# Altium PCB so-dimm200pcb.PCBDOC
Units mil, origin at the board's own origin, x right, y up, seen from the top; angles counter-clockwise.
Board outline 6000 x 4000 mil, 2 copper layers (Top Layer, Bottom Layer); 3 components, 0 nets, 611 pads, 0 vias.
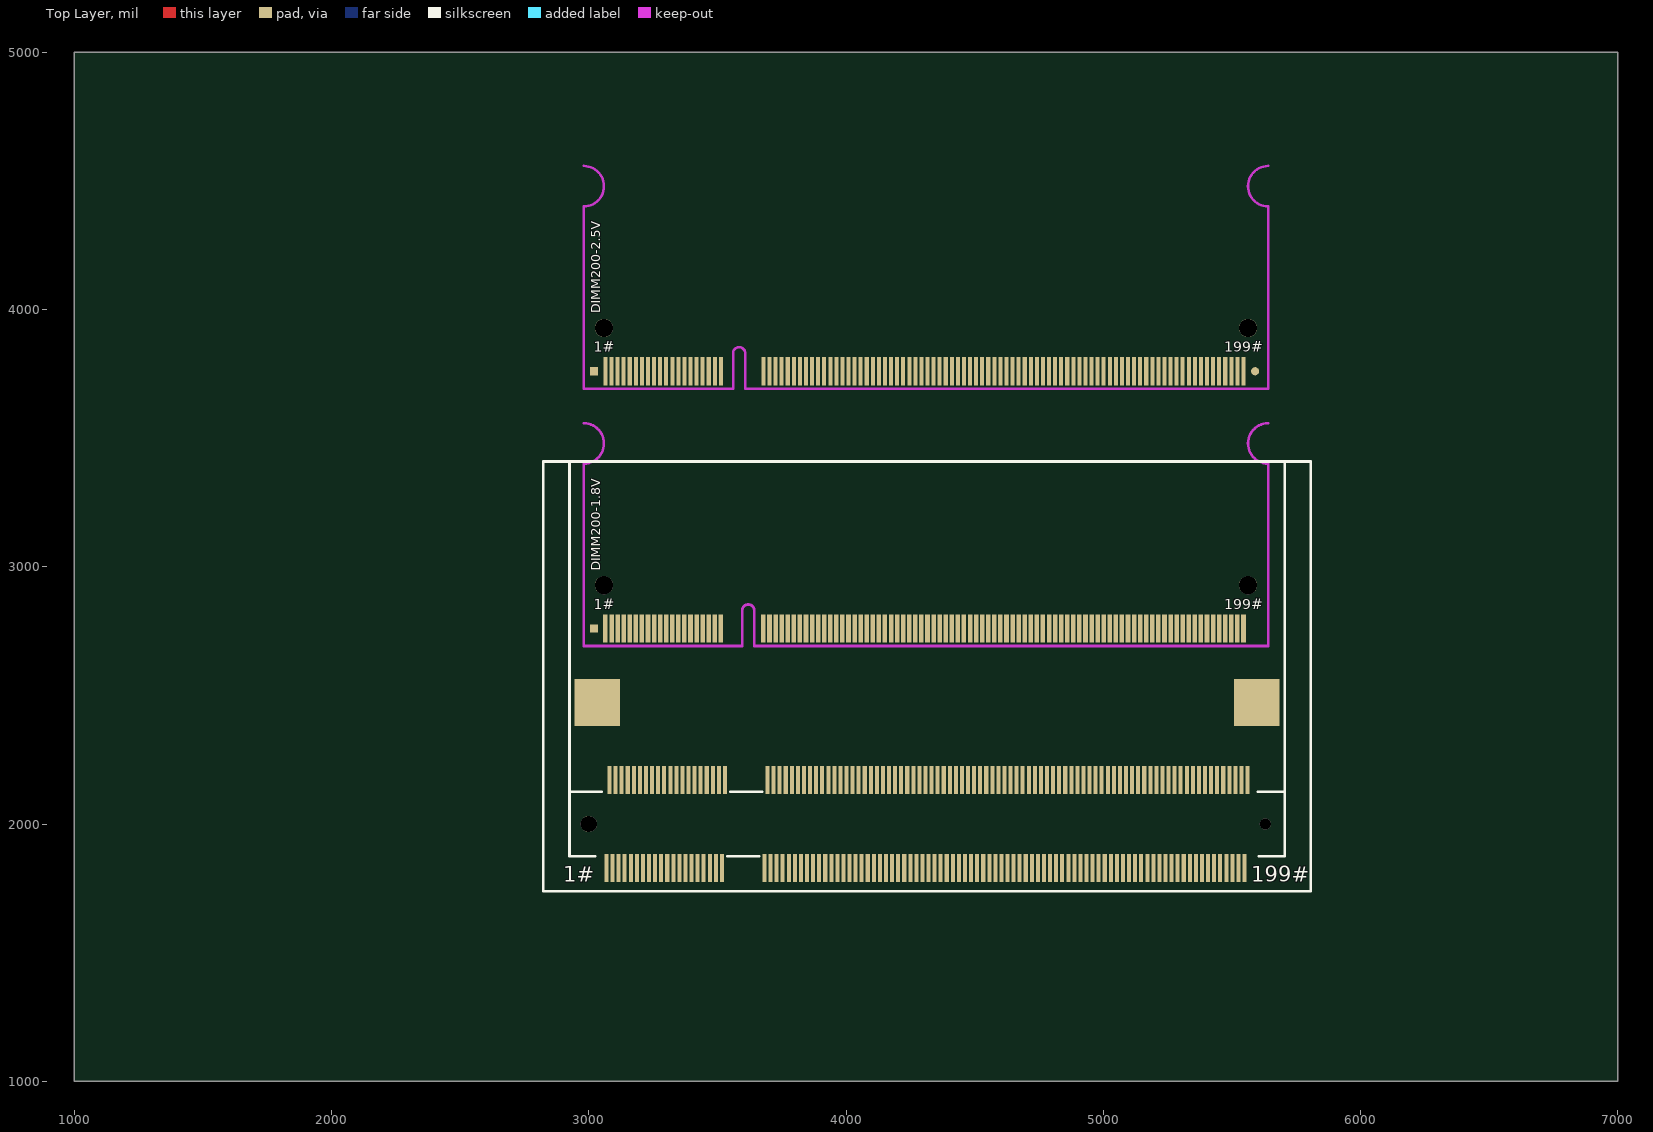
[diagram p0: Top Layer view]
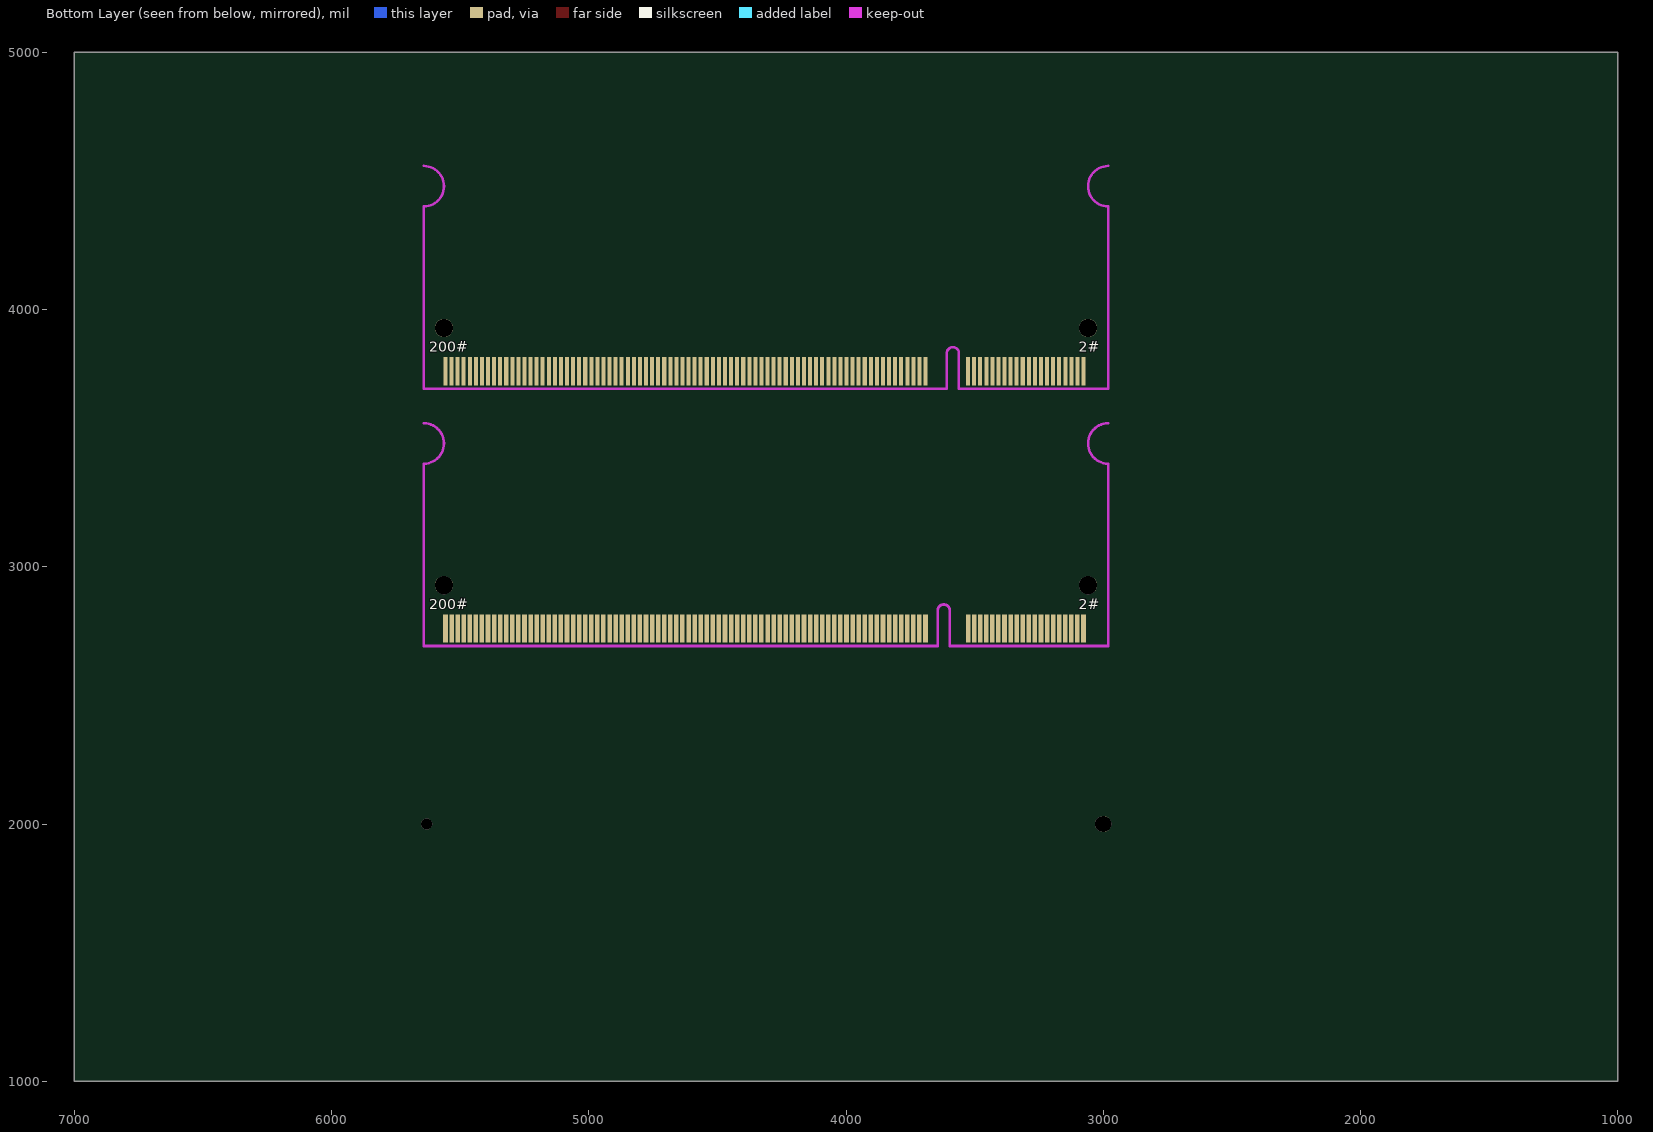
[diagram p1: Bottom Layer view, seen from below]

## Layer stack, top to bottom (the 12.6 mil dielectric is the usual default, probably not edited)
Top Layer: signal copper 1.4
Dielectric: dielectric 12.6, FR-4, Dk 4.8
Bottom Layer: signal copper 1.4

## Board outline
1000,1000 7000,1000 7000,5000 1000,5000

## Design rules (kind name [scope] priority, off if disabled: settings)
Clearance [All] p1: gap=10
ComponentClearance [All] p1: gap=10 collisioncheckmode=0
PolygonConnect [All] p1: connectstyle=Relief reliefconductorwidth=10 reliefentries=4 polygonreliefangle="90 Angle"
RoutingLayers [All] p1: top layer=Horizontal bottom layer=Vertical
RoutingVias [All] p1: holewidth=28 width=50 viastyle="Through Hole" minholewidth=28 minwidth=50 maxholewidth=28 maxwidth=50
SolderMaskExpansion [All] p1: expansion=4
TestPointUsage [All] p1: valid=0 allowmultiple=FALSE
Testpoint [All] p1: side=15 testpointundercomponent=TRUE minsize=40 maxsize=100 preferedsize=60 minholesize=0 maxholesize=40 preferedholesize=32 testpointgrid=1 style=1023 order=1234567890
Width [All] p1: maxlimit=10 minlimit=10 preferedwidth=10
16 further rules are at their usual default settings.

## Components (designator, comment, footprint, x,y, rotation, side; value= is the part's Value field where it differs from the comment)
? "Comment" "SO-DIMM200V25 " 3620,3760 r0 top
? "Comment" SO-DIMM200 3620,2760 r0 top
? "Comment" so-dimm200x 3000,2000 r0 top

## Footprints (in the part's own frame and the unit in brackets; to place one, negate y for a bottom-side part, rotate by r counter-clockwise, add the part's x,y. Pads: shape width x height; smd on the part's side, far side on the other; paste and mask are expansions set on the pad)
SO-DIMM200 [mm]
  round 1.8 hole 1.8: 0(-14.25,4.273) 0(49.35,4.273)
  rect 0.45x2.8 smd: A1(-14.1,0) A2(-13.5,0) A3(-12.9,0) A4(-12.3,0) A5(-11.7,0) A6(-11.1,0) A7(-10.5,0) A8(-9.9,0) A9(-9.3,0) A10(-8.7,0) A11(-8.1,0) A12(-7.5,0) A13(-6.9,0) A14(-6.3,0) A15(-5.7,0) A16(-5.1,0) A17(-4.5,0) A18(-3.9,0) A19(-3.3,0) A20(-2.7,0) A21(1.5,0) A22(2.1,0) A23(2.7,0) A24(3.3,0) A25(3.9,0) A26(4.5,0) A27(5.1,0) A28(5.7,0) A29(6.3,0) A30(6.9,0) A31(7.5,0) A32(8.1,0) A33(8.7,0) A34(9.3,0) A35(9.9,0) A36(10.5,0) A37(11.1,0) A38(11.7,0) A39(12.3,0) A40(12.9,0) A41(13.5,0) A42(14.1,0) A43(14.7,0) A44(15.3,0) A45(15.9,0) A46(16.5,0) A47(17.1,0) A48(17.7,0) A49(18.3,0) A50(18.9,0) A51(19.5,0) A52(20.1,0) A53(20.7,0) A54(21.3,0) A55(21.9,0) A56(22.5,0) A57(23.1,0) A58(23.7,0) A59(24.3,0) A60(24.9,0) A61(25.5,0) A62(26.1,0) A63(26.7,0) A64(27.3,0) A65(27.9,0) A66(28.5,0) A67(29.1,0) A68(29.7,0) A69(30.3,0) A70(30.9,0) A71(31.5,0) A72(32.1,0) A73(32.7,0) A74(33.3,0) A75(33.9,0) A76(34.5,0) A77(35.1,0) A78(35.7,0) A79(36.3,0) A80(36.9,0) A81(37.5,0) A82(38.1,0) A83(38.7,0) A84(39.3,0) A85(39.9,0) A86(40.5,0) A87(41.1,0) A88(41.7,0) A89(42.3,0) A90(42.9,0) A91(43.5,0) A92(44.1,0) A93(44.7,0) A94(45.3,0) A95(45.9,0) A96(46.5,0) A97(47.1,0) A98(47.7,0) A99(48.3,0) A100(48.9,0)
  rect 0.45x2.8 smd far side: B1(-13.8,0) B2(-13.2,0) B3(-12.6,0) B4(-12,0) B5(-11.4,0) B6(-10.8,0) B7(-10.2,0) B8(-9.6,0) B9(-9,0) B10(-8.4,0) B11(-7.8,0) B12(-7.2,0) B13(-6.6,0) B14(-6,0) B15(-5.4,0) B16(-4.8,0) B17(-4.2,0) B18(-3.6,0) B19(-3,0) B20(-2.4,0) B21(1.8,0) B22(2.4,0) B23(3,0) B24(3.6,0) B25(4.2,0) B26(4.8,0) B27(5.4,0) B28(6,0) B29(6.6,0) B30(7.2,0) B31(7.8,0) B32(8.4,0) B33(9,0) B34(9.6,0) B35(10.2,0) B36(10.8,0) B37(11.4,0) B38(12,0) B39(12.6,0) B40(13.2,0) B41(13.8,0) B42(14.4,0) B43(15,0) B44(15.6,0) B45(16.2,0) B46(16.8,0) B47(17.4,0) B48(18,0) B49(18.6,0) B50(19.2,0) B51(19.8,0) B52(20.4,0) B53(21,0) B54(21.6,0) B55(22.2,0) B56(22.8,0) B57(23.4,0) B58(24,0) B59(24.6,0) B60(25.2,0) B61(25.8,0) B62(26.4,0) B63(27,0) B64(27.6,0) B65(28.2,0) B66(28.8,0) B67(29.4,0) B68(30,0) B69(30.6,0) B70(31.2,0) B71(31.8,0) B72(32.4,0) B73(33,0) B74(33.6,0) B75(34.2,0) B76(34.8,0) B77(35.4,0) B78(36,0) B79(36.6,0) B80(37.2,0) B81(37.8,0) B82(38.4,0) B83(39,0) B84(39.6,0) B85(40.2,0) B86(40.8,0) B87(41.4,0) B88(42,0) B89(42.6,0) B90(43.2,0) B91(43.8,0) B92(44.4,0) B93(45,0) B94(45.6,0) B95(46.2,0) B96(46.8,0) B97(47.4,0) B98(48,0) B99(48.6,0) B100(49.2,0)
  rect 0.8x0.8 smd: ""(-15.24,0)
  Keep-Out Layer lines w0.254: -16.25,20.273 cw(c-16.25,18.273) -16.25,16.273 -16.25,-1.727 -0.6,-1.727 -0.6,1.773 cw(c0,1.773) 0.6,1.773 0.6,-1.727 51.35,-1.727 51.35,16.273 cw(c51.35,18.273) 51.35,20.273
"SO-DIMM200V25 " [mm]
  round 1.8 hole 1.8: 0(-14.25,4.273) 0(49.35,4.273)
  rect 0.4x2.8 smd: A1(-14.1,0) A2(-13.5,0) A3(-12.9,0) A4(-12.3,0) A5(-11.7,0) A6(-11.1,0) A7(-10.5,0) A8(-9.9,0) A9(-9.3,0) A10(-8.7,0) A11(-8.1,0) A12(-7.5,0) A13(-6.9,0) A14(-6.3,0) A15(-5.7,0) A16(-5.1,0) A17(-4.5,0) A18(-3.9,0) A19(-3.3,0) A20(-2.7,0) A21(1.5,0) A22(2.1,0) A23(2.7,0) A24(3.3,0) A25(3.9,0) A26(4.5,0) A27(5.1,0) A28(5.7,0) A29(6.3,0) A30(6.9,0) A31(7.5,0) A32(8.1,0) A33(8.7,0) A34(9.3,0) A35(9.9,0) A36(10.5,0) A37(11.1,0) A38(11.7,0) A39(12.3,0) A40(12.9,0) A41(13.5,0) A42(14.1,0) A43(14.7,0) A44(15.3,0) A45(15.9,0) A46(16.5,0) A47(17.1,0) A48(17.7,0) A49(18.3,0) A50(18.9,0) A51(19.5,0) A52(20.1,0) A53(20.7,0) A54(21.3,0) A55(21.9,0) A56(22.5,0) A57(23.1,0) A58(23.7,0) A59(24.3,0) A60(24.9,0) A61(25.5,0) A62(26.1,0) A63(26.7,0) A64(27.3,0) A65(27.9,0) A66(28.5,0) A67(29.1,0) A68(29.7,0) A69(30.3,0) A70(30.9,0) A71(31.5,0) A72(32.1,0) A73(32.7,0) A74(33.3,0) A75(33.9,0) A76(34.5,0) A77(35.1,0) A78(35.7,0) A79(36.3,0) A80(36.9,0) A81(37.5,0) A82(38.1,0) A83(38.7,0) A84(39.3,0) A85(39.9,0) A86(40.5,0) A87(41.1,0) A88(41.7,0) A89(42.3,0) A90(42.9,0) A91(43.5,0) A92(44.1,0) A93(44.7,0) A94(45.3,0) A95(45.9,0) A96(46.5,0) A97(47.1,0) A98(47.7,0) A99(48.3,0) A100(48.9,0)
  rect 0.4x2.8 smd far side: B1(-13.8,0) B2(-13.2,0) B3(-12.6,0) B4(-12,0) B5(-11.4,0) B6(-10.8,0) B7(-10.2,0) B8(-9.6,0) B9(-9,0) B10(-8.4,0) B11(-7.8,0) B12(-7.2,0) B13(-6.6,0) B14(-6,0) B15(-5.4,0) B16(-4.8,0) B17(-4.2,0) B18(-3.6,0) B19(-3,0) B20(-2.4,0) B21(1.8,0) B22(2.4,0) B23(3,0) B24(3.6,0) B25(4.2,0) B26(4.8,0) B27(5.4,0) B28(6,0) B29(6.6,0) B30(7.2,0) B31(7.8,0) B32(8.4,0) B33(9,0) B34(9.6,0) B35(10.2,0) B36(10.8,0) B37(11.4,0) B38(12,0) B39(12.6,0) B40(13.2,0) B41(13.8,0) B42(14.4,0) B43(15,0) B44(15.6,0) B45(16.2,0) B46(16.8,0) B47(17.4,0) B48(18,0) B49(18.6,0) B50(19.2,0) B51(19.8,0) B52(20.4,0) B53(21,0) B54(21.6,0) B55(22.2,0) B56(22.8,0) B57(23.4,0) B58(24,0) B59(24.6,0) B60(25.2,0) B61(25.8,0) B62(26.4,0) B63(27,0) B64(27.6,0) B65(28.2,0) B66(28.8,0) B67(29.4,0) B68(30,0) B69(30.6,0) B70(31.2,0) B71(31.8,0) B72(32.4,0) B73(33,0) B74(33.6,0) B75(34.2,0) B76(34.8,0) B77(35.4,0) B78(36,0) B79(36.6,0) B80(37.2,0) B81(37.8,0) B82(38.4,0) B83(39,0) B84(39.6,0) B85(40.2,0) B86(40.8,0) B87(41.4,0) B88(42,0) B89(42.6,0) B90(43.2,0) B91(43.8,0) B92(44.4,0) B93(45,0) B94(45.6,0) B95(46.2,0) B96(46.8,0) B97(47.4,0) B98(48,0) B99(48.6,0) B100(49.2,0)
  rect 0.8x0.8 smd: ""(-15.24,0)
  round 0.8 smd: ""(50.04,0)
  Keep-Out Layer lines w0.254: -16.25,20.273 cw(c-16.25,18.273) -16.25,16.273 -16.25,-1.727 -1.5,-1.727 -1.5,1.773 cw(c-0.9,1.773) -0.3,1.773 -0.3,-1.727 51.35,-1.727 51.35,16.273 cw(c51.35,18.273) 51.35,20.273
so-dimm200x [mm]
  round 1.6 hole 1.6: 0(0,0)
  rect 4.5x4.6 smd: 0(0.85,12) 0(65.95,12)
  round 1.1 hole 1.1: 0(66.8,0)
  rect 0.4x2.8 smd: A1(1.75,-4.35) A2(2.35,-4.35) A3(2.95,-4.35) A4(3.55,-4.35) A5(4.15,-4.35) A6(4.75,-4.35) A7(5.35,-4.35) A8(5.95,-4.35) A9(6.55,-4.35) A10(7.15,-4.35) A11(7.75,-4.35) A12(8.35,-4.35) A13(8.95,-4.35) A14(9.55,-4.35) A15(10.15,-4.35) A16(10.75,-4.35) A17(11.35,-4.35) A18(11.95,-4.35) A19(12.55,-4.35) A20(13.15,-4.35) A21(17.35,-4.35) A22(17.95,-4.35) A23(18.55,-4.35) A24(19.15,-4.35) A25(19.75,-4.35) A26(20.35,-4.35) A27(20.95,-4.35) A28(21.55,-4.35) A29(22.15,-4.35) A30(22.75,-4.35) A31(23.35,-4.35) A32(23.95,-4.35) A33(24.55,-4.35) A34(25.15,-4.35) A35(25.75,-4.35) A36(26.35,-4.35) A37(26.95,-4.35) A38(27.55,-4.35) A39(28.15,-4.35) A40(28.75,-4.35) A41(29.35,-4.35) A42(29.95,-4.35) A43(30.55,-4.35) A44(31.15,-4.35) A45(31.75,-4.35) A46(32.35,-4.35) A47(32.95,-4.35) A48(33.55,-4.35) A49(34.15,-4.35) A50(34.75,-4.35) A51(35.35,-4.35) A52(35.95,-4.35) A53(36.55,-4.35) A54(37.15,-4.35) A55(37.75,-4.35) A56(38.35,-4.35) A57(38.95,-4.35) A58(39.55,-4.35) A59(40.15,-4.35) A60(40.75,-4.35) A61(41.35,-4.35) A62(41.95,-4.35) A63(42.55,-4.35) A64(43.15,-4.35) A65(43.75,-4.35) A66(44.35,-4.35) A67(44.95,-4.35) A68(45.55,-4.35) A69(46.15,-4.35) A70(46.75,-4.35) A71(47.35,-4.35) A72(47.95,-4.35) A73(48.55,-4.35) A74(49.15,-4.35) A75(49.75,-4.35) A76(50.35,-4.35) A77(50.95,-4.35) A78(51.55,-4.35) A79(52.15,-4.35) A80(52.75,-4.35) A81(53.35,-4.35) A82(53.95,-4.35) A83(54.55,-4.35) A84(55.15,-4.35) A85(55.75,-4.35) A86(56.35,-4.35) A87(56.95,-4.35) A88(57.55,-4.35) A89(58.15,-4.35) A90(58.75,-4.35) A91(59.35,-4.35) A92(59.95,-4.35) A93(60.55,-4.35) A94(61.15,-4.35) A95(61.75,-4.35) A96(62.35,-4.35) A97(62.95,-4.35) A98(63.55,-4.35) A99(64.15,-4.35) A100(64.75,-4.35) B1(2.05,4.35) B2(2.65,4.35) B3(3.25,4.35) B4(3.85,4.35) B5(4.45,4.35) B6(5.05,4.35) B7(5.65,4.35) B8(6.25,4.35) B9(6.85,4.35) B10(7.45,4.35) B11(8.05,4.35) B12(8.65,4.35) B13(9.25,4.35) B14(9.85,4.35) B15(10.45,4.35) B16(11.05,4.35) B17(11.65,4.35) B18(12.25,4.35) B19(12.85,4.35) B20(13.45,4.35) B21(17.65,4.35) B22(18.25,4.35) B23(18.85,4.35) B24(19.45,4.35) B25(20.05,4.35) B26(20.65,4.35) B27(21.25,4.35) B28(21.85,4.35) B29(22.45,4.35) B30(23.05,4.35) B31(23.65,4.35) B32(24.25,4.35) B33(24.85,4.35) B34(25.45,4.35) B35(26.05,4.35) B36(26.65,4.35) B37(27.25,4.35) B38(27.85,4.35) B39(28.45,4.35) B40(29.05,4.35) B41(29.65,4.35) B42(30.25,4.35) B43(30.85,4.35) B44(31.45,4.35) B45(32.05,4.35) B46(32.65,4.35) B47(33.25,4.35) B48(33.85,4.35) B49(34.45,4.35) B50(35.05,4.35) B51(35.65,4.35) B52(36.25,4.35) B53(36.85,4.35) B54(37.45,4.35) B55(38.05,4.35) B56(38.65,4.35) B57(39.25,4.35) B58(39.85,4.35) B59(40.45,4.35) B60(41.05,4.35) B61(41.65,4.35) B62(42.25,4.35) B63(42.85,4.35) B64(43.45,4.35) B65(44.05,4.35) B66(44.65,4.35) B67(45.25,4.35) B68(45.85,4.35) B69(46.45,4.35) B70(47.05,4.35) B71(47.65,4.35) B72(48.25,4.35) B73(48.85,4.35) B74(49.45,4.35) B75(50.05,4.35) B76(50.65,4.35) B77(51.25,4.35) B78(51.85,4.35) B79(52.45,4.35) B80(53.05,4.35) B81(53.65,4.35) B82(54.25,4.35) B83(54.85,4.35) B84(55.45,4.35) B85(56.05,4.35) B86(56.65,4.35) B87(57.25,4.35) B88(57.85,4.35) B89(58.45,4.35) B90(59.05,4.35) B91(59.65,4.35) B92(60.25,4.35) B93(60.85,4.35) B94(61.45,4.35) B95(62.05,4.35) B96(62.65,4.35) B97(63.25,4.35) B98(63.85,4.35) B99(64.45,4.35) B100(65.05,4.35)
  silkscreen extent -4.5,-6.64 71.3,35.8

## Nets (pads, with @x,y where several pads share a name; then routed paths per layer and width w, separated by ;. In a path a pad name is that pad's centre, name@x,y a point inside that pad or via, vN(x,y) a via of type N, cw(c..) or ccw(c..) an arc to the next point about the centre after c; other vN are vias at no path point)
pads on no net: ?. ?.0 ?.A1 ?.A2 ?.A3 ?.A4 ?.A5 ?.A6 ?.A7 ?.A8 ?.A9 ?.A10 ?.A11 ?.A12 ?.A13 ?.A14 ?.A15 ?.A16 ?.A17 ?.A18 ?.A19 ?.A20 ?.A21 ?.A22 ?.A23 ?.A24 ?.A25 ?.A26 ?.A27 ?.A28 ?.A29 ?.A30 ?.A31 ?.A32 ?.A33 ?.A34 ?.A35 ?.A36 ?.A37 ?.A38 ?.A39 ?.A40 ?.A41 ?.A42 ?.A43 ?.A44 ?.A45 ?.A46 ?.A47 ?.A48 ?.A49 ?.A50 ?.A51 ?.A52 ?.A53 ?.A54 ?.A55 ?.A56 ?.A57 ?.A58 ?.A59 ?.A60 ?.A61 ?.A62 ?.A63 ?.A64 ?.A65 ?.A66 ?.A67 ?.A68 ?.A69 ?.A70 ?.A71 ?.A72 ?.A73 ?.A74 ?.A75 ?.A76 ?.A77 ?.A78 ?.A79 ?.A80 ?.A81 ?.A82 ?.A83 ?.A84 ?.A85 ?.A86 ?.A87 ?.A88 ?.A89 ?.A90 ?.A91 ?.A92 ?.A93 ?.A94 ?.A95 ?.A96 ?.A97 ?.A98 ?.A99 ?.A100 ?.B1 ?.B2 ?.B3 ?.B4 ?.B5 ?.B6 ?.B7 ?.B8 ?.B9 ?.B10 ?.B11 ?.B12 ?.B13 ?.B14 ?.B15 ?.B16 ?.B17 ?.B18 ?.B19 ?.B20 ?.B21 ?.B22 ?.B23 ?.B24 ?.B25 ?.B26 ?.B27 ?.B28 ?.B29 ?.B30 ?.B31 ?.B32 ?.B33 ?.B34 ?.B35 ?.B36 ?.B37 ?.B38 ?.B39 ?.B40 ?.B41 ?.B42 ?.B43 ?.B44 ?.B45 ?.B46 ?.B47 ?.B48 ?.B49 ?.B50 ?.B51 ?.B52 ?.B53 ?.B54 ?.B55 ?.B56 ?.B57 ?.B58 ?.B59 ?.B60 ?.B61 ?.B62 ?.B63 ?.B64 ?.B65 ?.B66 ?.B67 ?.B68 ?.B69 ?.B70 ?.B71 ?.B72 ?.B73 ?.B74 ?.B75 ?.B76 ?.B77 ?.B78 ?.B79 ?.B80 ?.B81 ?.B82 ?.B83 ?.B84 ?.B85 ?.B86 ?.B87 ?.B88 ?.B89 ?.B90 ?.B91 ?.B92 ?.B93 ?.B94 ?.B95 ?.B96 ?.B97 ?.B98 ?.B99 ?.B100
